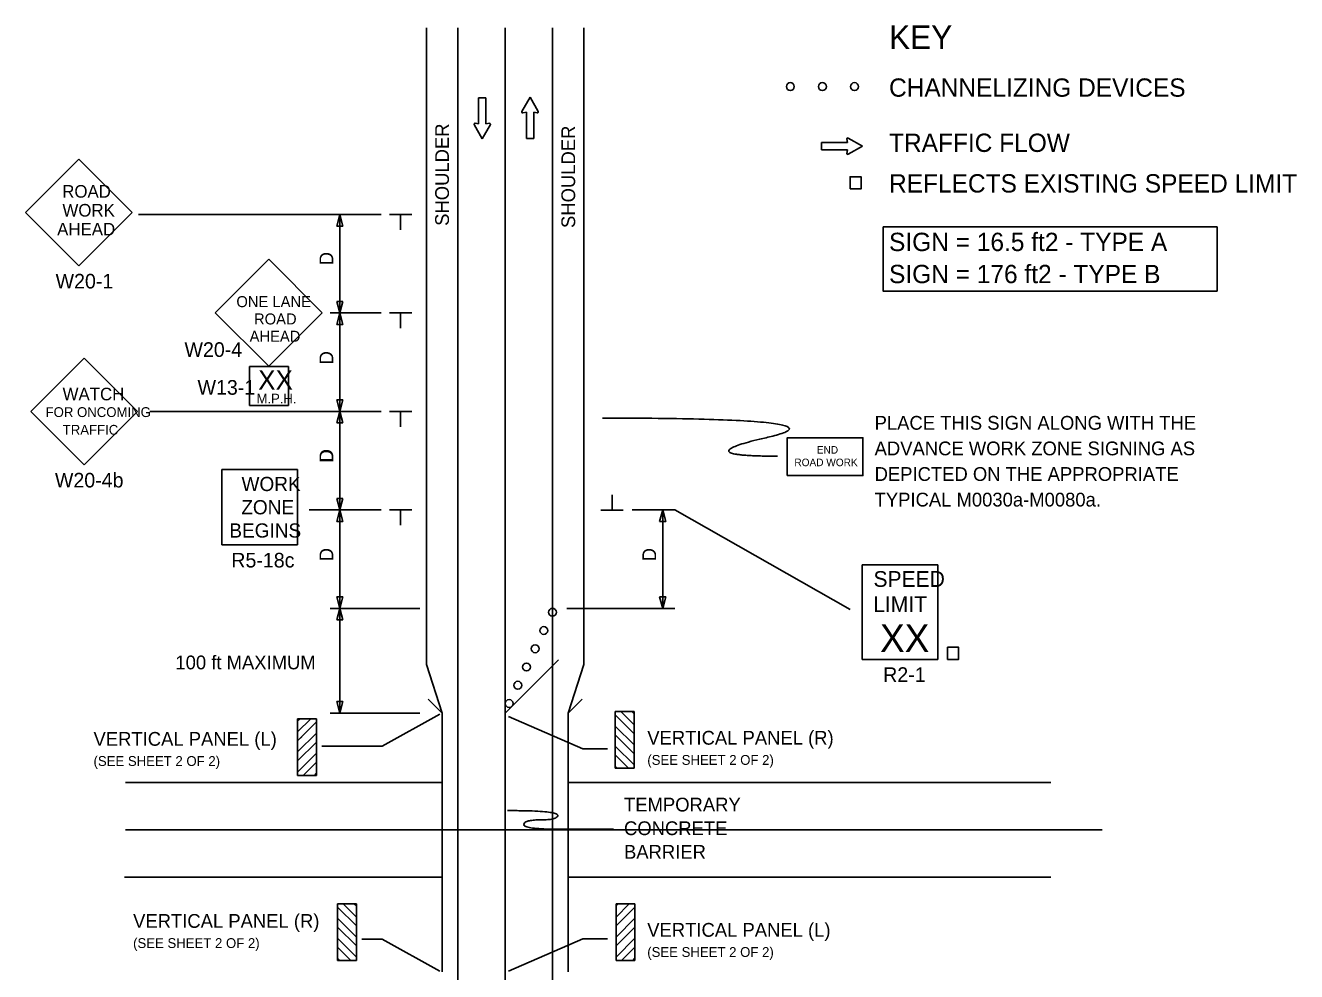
# Model space of a CAD drawing. Extents: x 16768 to 18475, y 7218 to 8259.
# Drawn here: x 16768 to 17414, y 7706 to 8187 of the extents above; entities that cross this region are included whole.
import ezdxf

# ---------------------------------------------------------------- set-up
doc = ezdxf.new("R2010")
doc.units = 0
for name, color, linetype in [('MT_SCRATCH_LEVEL_E', 7, 'Continuous'), ('PAVT_EDGE_EX', 7, 'Continuous'), ('TRAFFIC_SIGNS_PR', 7, 'Continuous'), ('TYPICAL_TEXT_DIMEN_EX', 7, 'Continuous'), ('TYPICAL_TEXT_DIMEN_PR', 7, 'Continuous')]:
    doc.layers.add(name, color=color, linetype=linetype)

msp = doc.modelspace()

# ---------------------------------------------------------------- linework, layer by layer
at = {"layer": 'MT_SCRATCH_LEVEL_E'}
for p, q in [((17002.27, 8150.09), (16998.52, 8150.09)), ((16998.52, 8150.09), (16998.52, 8136.83)), ((17002.27, 8150.09), (16998.52, 8150.09)), ((16998.52, 8150.09), (16998.52, 8136.83)), ((17002.27, 8136.83), (17002.27, 8150.09)), ((17002.27, 8136.83), (17002.27, 8150.09)), ((17024.66, 8150.35), (17020.55, 8143.11)), ((17024.66, 8150.35), (17020.55, 8143.11)), ((17028.81, 8143.11), (17024.66, 8150.35)), ((17028.81, 8143.11), (17024.66, 8150.35)), ((16996.27, 8136.47), (17000.41, 8129.22)), ((16996.27, 8136.47), (17000.41, 8129.22)), ((16998.52, 8136.83), (16996.75, 8137.15)), ((16998.52, 8136.83), (16996.75, 8137.15)), ((17000.41, 8129.22), (17004.53, 8136.47)), ((17000.41, 8129.22), (17004.53, 8136.47)), ((17004.04, 8137.15), (17002.27, 8136.83)), ((17004.04, 8137.15), (17002.27, 8136.83)), ((17021.03, 8142.43), (17022.81, 8142.74)), ((17021.03, 8142.43), (17022.81, 8142.74)), ((17022.81, 8142.74), (17022.81, 8129.49)), ((17022.81, 8142.74), (17022.81, 8129.49)), ((17026.55, 8129.49), (17026.55, 8142.74)), ((17026.55, 8142.74), (17028.33, 8142.43)), ((17026.55, 8129.49), (17026.55, 8142.74)), ((17026.55, 8142.74), (17028.33, 8142.43)), ((17022.81, 8129.49), (17026.55, 8129.49)), ((17022.81, 8129.49), (17026.55, 8129.49)), ((17185.97, 8127.41), (17172.71, 8127.41)), ((17172.71, 8127.41), (17172.71, 8123.67)), ((17185.97, 8127.41), (17172.71, 8127.41)), ((17172.71, 8127.41), (17172.71, 8123.67)), ((17172.71, 8123.67), (17185.97, 8123.67)), ((17172.71, 8123.67), (17185.97, 8123.67)), ((17185.65, 8129.19), (17185.97, 8127.41)), ((17185.65, 8129.19), (17185.97, 8127.41)), ((17185.97, 8123.67), (17185.65, 8121.89)), ((17185.97, 8123.67), (17185.65, 8121.89)), ((17193.57, 8125.56), (17186.33, 8129.67)), ((17193.57, 8125.56), (17186.33, 8129.67)), ((17186.33, 8121.41), (17193.57, 8125.56)), ((17186.33, 8121.41), (17193.57, 8125.56))]:
    msp.add_line(p, q, dxfattribs=at)
for centre, start, end in [((17020.95, 8142.89), 150.42484, 279.96381), ((17020.95, 8142.89), 150.42484, 279.96381), ((17028.4, 8142.89), 260.03619, 29.77312), ((17028.4, 8142.89), 260.03619, 29.77312), ((16996.68, 8136.69), 80.03619, 209.77312), ((16996.68, 8136.69), 80.03619, 209.77312), ((17004.12, 8136.69), 330.42484, 99.96381), ((17004.12, 8136.69), 330.42484, 99.96381), ((17186.11, 8129.26), 60.42484, 189.96381), ((17186.11, 8129.26), 60.42484, 189.96381), ((17186.11, 8121.82), 170.03619, 299.77312), ((17186.11, 8121.82), 170.03619, 299.77312)]:
    msp.add_arc(centre, 0.463, start, end, dxfattribs=at)
at = {"layer": 'PAVT_EDGE_EX'}
for p, q in [((16972.07, 8185.68), (16972.07, 7862.31)), ((16988.07, 8185.68), (16988.07, 7363.75)), ((17012.07, 8185.68), (17012.07, 7363.75)), ((17036.07, 8185.68), (17036.07, 7363.75)), ((17052.07, 8185.68), (17052.07, 7862.31)), ((16972.07, 7862.31), (16980.07, 7837.6)), ((17012.07, 7837.6), (17039.08, 7864.62)), ((17044.07, 7837.6), (17052.07, 7862.31)), ((16980.07, 7837.6), (16973, 7844.68)), ((17044.07, 7837.6), (17051.14, 7844.68)), ((16980.07, 7837.6), (16980.07, 7706.21)), ((17012.07, 7837.6), (17012.07, 7706.21)), ((17044.07, 7837.6), (17044.07, 7706.21)), ((16819.22, 7802.34), (16980.07, 7802.34)), ((16819.22, 7802.34), (16980.07, 7802.34)), ((17044.07, 7802.34), (17289.26, 7802.34)), ((16819.22, 7778.34), (17315.26, 7778.34)), ((16818.7, 7754.34), (16980.07, 7754.34)), ((17044.07, 7754.34), (17289.26, 7754.34))]:
    msp.add_line(p, q, dxfattribs=at)
for points in [[(17012.07, 8185.68), (17012.07, 8160.68)], [(17012.07, 8085.68), (17012.07, 8060.68)], [(17012.07, 7985.68), (17012.07, 7960.68)], [(17012.07, 7885.68), (17012.07, 7860.68)], [(16819.22, 7778.34), (16844.22, 7778.34)], [(16919.22, 7778.34), (16944.22, 7778.34)], [(17119.22, 7778.34), (17144.22, 7778.34)], [(17219.22, 7778.34), (17244.22, 7778.34)]]:
    msp.add_lwpolyline(points, dxfattribs=at)
at = {"layer": 'TRAFFIC_SIGNS_PR'}
for p, q in [((16795.49, 8119.01), (16768.34, 8091.86)), ((16822.64, 8091.86), (16795.49, 8119.01)), ((16768.34, 8091.86), (16795.49, 8064.7)), ((16795.49, 8064.7), (16822.64, 8091.86)), ((16891.93, 8068.07), (16864.78, 8040.92)), ((16919.08, 8040.92), (16891.93, 8068.07)), ((16864.78, 8040.92), (16891.93, 8013.77)), ((16891.93, 8013.77), (16919.08, 8040.92)), ((16798.17, 8017.94), (16771.02, 7990.79)), ((16825.32, 7990.79), (16798.17, 8017.94)), ((16882.14, 8013.61), (16901.99, 8013.61)), ((16882.14, 7993.76), (16882.14, 8013.61)), ((16901.99, 7993.76), (16901.99, 8013.61)), ((16771.02, 7990.79), (16798.17, 7963.64)), ((16798.17, 7963.64), (16825.32, 7990.79)), ((16882.14, 7993.76), (16901.99, 7993.76)), ((16868.12, 7923.01), (16868.12, 7961.41)), ((16868.12, 7961.41), (16906.52, 7961.41)), ((16906.52, 7923.01), (16906.52, 7961.41)), ((16868.12, 7923.01), (16906.52, 7923.01)), ((17193.38, 7912.88), (17231.78, 7912.88)), ((17193.38, 7864.88), (17193.38, 7912.88)), ((17231.78, 7864.88), (17231.78, 7912.88)), ((17193.38, 7864.88), (17231.78, 7864.88)), ((16906.63, 7834.79), (16916.23, 7834.79)), ((16906.63, 7834.79), (16906.63, 7805.99)), ((16906.63, 7833.71), (16907.71, 7834.79)), ((16906.63, 7828.05), (16913.37, 7834.79)), ((16906.63, 7823.52), (16916.23, 7833.12)), ((16916.23, 7834.79), (16916.23, 7805.99)), ((17077.5, 7838.39), (17067.9, 7838.39)), ((17067.9, 7838.39), (17067.9, 7809.59)), ((17077.5, 7827.12), (17067.9, 7836.72)), ((17077.5, 7831.64), (17070.76, 7838.39)), ((17077.5, 7837.3), (17076.42, 7838.39)), ((17077.5, 7838.39), (17077.5, 7809.59)), ((16906.63, 7817.87), (16916.23, 7827.47)), ((17077.5, 7821.46), (17067.9, 7831.06)), ((17077.5, 7816.93), (17067.9, 7826.53)), ((16906.63, 7813.34), (16916.23, 7822.94)), ((16908.04, 7824.94), (16909.46, 7826.35)), ((17077.5, 7811.28), (17067.9, 7820.88)), ((16906.63, 7807.68), (16916.23, 7817.28)), ((17074.67, 7809.59), (17067.9, 7816.35)), ((16909.46, 7805.99), (16916.23, 7812.76)), ((16915.12, 7805.99), (16916.23, 7807.1)), ((17069.01, 7809.59), (17067.9, 7810.69)), ((17077.5, 7809.59), (17067.9, 7809.59)), ((16906.63, 7805.99), (16916.23, 7805.99)), ((16936.47, 7740.81), (16926.87, 7740.81)), ((16926.87, 7740.81), (16926.87, 7712.01)), ((16936.47, 7729.54), (16926.87, 7739.14)), ((16936.47, 7734.06), (16929.73, 7740.81)), ((16936.47, 7739.72), (16935.39, 7740.81)), ((16936.47, 7740.81), (16936.47, 7712.01)), ((17068.37, 7740.81), (17077.97, 7740.81)), ((17068.37, 7740.81), (17068.37, 7712.01)), ((17068.37, 7739.72), (17069.46, 7740.81)), ((17068.37, 7734.06), (17075.12, 7740.81)), ((17068.37, 7729.54), (17077.97, 7739.14)), ((17077.97, 7740.81), (17077.97, 7712.01)), ((16936.47, 7723.88), (16926.87, 7733.48)), ((17068.37, 7723.88), (17077.97, 7733.48)), ((17069.79, 7730.95), (17071.2, 7732.36)), ((16936.47, 7719.35), (16926.87, 7728.95)), ((16936.47, 7713.7), (16926.87, 7723.3)), ((17068.37, 7719.35), (17077.97, 7728.95)), ((17068.37, 7713.7), (17077.97, 7723.3)), ((16933.64, 7712.01), (16926.87, 7718.77)), ((17071.21, 7712.01), (17077.97, 7718.77)), ((16927.98, 7712.01), (16926.87, 7713.11)), ((16936.47, 7712.01), (16926.87, 7712.01)), ((17068.37, 7712.01), (17077.97, 7712.01)), ((17076.87, 7712.01), (17077.97, 7713.11))]:
    msp.add_line(p, q, dxfattribs=at)
for points in [[(17187.22, 8103.84), (17192.82, 8103.84), (17192.82, 8110.01), (17187.22, 8110.01)], [(17155.35, 7958.27), (17193.75, 7958.27), (17193.75, 7977.47), (17155.35, 7977.47)], [(17236.8, 7864.88), (17242.39, 7864.88), (17242.39, 7871.05), (17236.8, 7871.05)], [(16907.71, 7834.79), (16913.37, 7834.79), (16906.63, 7828.05), (16906.63, 7833.71)], [(16906.63, 7823.52), (16916.23, 7833.12), (16916.23, 7827.47), (16906.63, 7817.87)], [(17077.5, 7827.12), (17067.9, 7836.72), (17067.9, 7831.06), (17077.5, 7821.46)], [(17076.42, 7838.39), (17070.76, 7838.39), (17077.5, 7831.64), (17077.5, 7837.3)], [(17077.5, 7816.93), (17067.9, 7826.53), (17067.9, 7820.88), (17077.5, 7811.28)], [(16906.63, 7813.34), (16916.23, 7822.94), (16916.23, 7817.28), (16906.63, 7807.68)], [(17067.9, 7816.35), (17067.9, 7810.69), (17069.01, 7809.59), (17074.67, 7809.59)], [(16916.23, 7812.76), (16916.23, 7807.1), (16915.12, 7805.99), (16909.46, 7805.99)], [(16936.47, 7729.54), (16926.87, 7739.14), (16926.87, 7733.48), (16936.47, 7723.88)], [(16935.39, 7740.81), (16929.73, 7740.81), (16936.47, 7734.06), (16936.47, 7739.72)], [(17069.46, 7740.81), (17075.12, 7740.81), (17068.37, 7734.06), (17068.37, 7739.72)], [(17068.37, 7729.54), (17077.97, 7739.14), (17077.97, 7733.48), (17068.37, 7723.88)], [(16936.47, 7719.35), (16926.87, 7728.95), (16926.87, 7723.3), (16936.47, 7713.7)], [(17068.37, 7719.35), (17077.97, 7728.95), (17077.97, 7723.3), (17068.37, 7713.7)], [(16926.87, 7718.77), (16926.87, 7713.11), (16927.98, 7712.01), (16933.64, 7712.01)], [(17077.97, 7718.77), (17077.97, 7713.11), (17076.87, 7712.01), (17071.21, 7712.01)]]:
    msp.add_lwpolyline(points, close=True, dxfattribs=at)
for centre in [(17156.9, 8155.81), (17173.2, 8155.81), (17189.5, 8155.81), (17036.07, 7888.82), (17031.67, 7879.55), (17027.27, 7870.29), (17022.87, 7861.03), (17018.47, 7851.76), (17014.07, 7842.5)]:
    msp.add_circle(centre, 2, dxfattribs=at)
msp.add_open_spline([(17150.44, 7968.1), (17103.21, 7968.1), (17188.23, 7987.44), (17061.55, 7987.44)], degree=2, dxfattribs=at)
at = {"layer": 'TYPICAL_TEXT_DIMEN_EX'}
msp.add_lwpolyline([(17204.02, 8084.5), (17373.68, 8084.5), (17373.68, 8051.95), (17204.02, 8051.95)], close=True, dxfattribs=at)
at = {"layer": 'TYPICAL_TEXT_DIMEN_PR'}
for p, q in [((16825.83, 8090.82), (16949.07, 8090.82)), ((16926.5, 8084.96), (16928.07, 8090.82)), ((16928.07, 8084.96), (16926.5, 8084.96)), ((16928.07, 8090.82), (16928.07, 8040.82)), ((16928.07, 8090.82), (16929.64, 8084.96)), ((16929.64, 8084.96), (16928.07, 8084.96)), ((16953.32, 8090.82), (16964.57, 8090.82)), ((16958.94, 8090.82), (16958.94, 8083.04)), ((16928.07, 8040.82), (16926.5, 8046.68)), ((16926.5, 8046.68), (16928.07, 8046.68)), ((16928.07, 8040.82), (16926.5, 8046.68)), ((16926.5, 8046.68), (16928.07, 8046.68)), ((16928.07, 8046.68), (16929.64, 8046.68)), ((16929.64, 8046.68), (16928.07, 8040.82)), ((16928.07, 8046.68), (16929.64, 8046.68)), ((16929.64, 8046.68), (16928.07, 8040.82)), ((16923.07, 8040.82), (16949.07, 8040.82)), ((16926.5, 8034.96), (16928.07, 8040.82)), ((16928.07, 8040.82), (16928.07, 7990.82)), ((16928.07, 8040.82), (16929.64, 8034.96)), ((16953.32, 8040.82), (16964.57, 8040.82)), ((16958.94, 8040.82), (16958.94, 8033.04)), ((16928.07, 8034.96), (16926.5, 8034.96)), ((16929.64, 8034.96), (16928.07, 8034.96)), ((16928.07, 7990.82), (16926.5, 7996.68)), ((16926.5, 7996.68), (16928.07, 7996.68)), ((16928.07, 7996.68), (16929.64, 7996.68)), ((16929.64, 7996.68), (16928.07, 7990.82)), ((16831.47, 7990.82), (16949.07, 7990.82)), ((16926.5, 7984.96), (16928.07, 7990.82)), ((16928.07, 7990.82), (16929.64, 7984.96)), ((16928.07, 7990.82), (16928.07, 7940.82)), ((16953.32, 7990.82), (16964.57, 7990.82)), ((16958.94, 7990.82), (16958.94, 7983.04)), ((16928.07, 7984.96), (16926.5, 7984.96)), ((16929.64, 7984.96), (16928.07, 7984.96)), ((16928.07, 7940.82), (16926.5, 7946.68)), ((16926.5, 7946.68), (16928.07, 7946.68)), ((16928.07, 7946.68), (16929.64, 7946.68)), ((16929.64, 7946.68), (16928.07, 7940.82)), ((17066.32, 7940.76), (17066.32, 7948.54)), ((16912.51, 7940.82), (16949.07, 7940.82)), ((16926.5, 7934.96), (16928.07, 7940.82)), ((16928.07, 7940.82), (16928.07, 7890.82)), ((16928.07, 7940.82), (16929.64, 7934.96)), ((16953.32, 7940.82), (16964.57, 7940.82)), ((16958.94, 7940.82), (16958.94, 7933.04)), ((17071.94, 7940.76), (17060.69, 7940.76)), ((17076.51, 7940.82), (17098.25, 7940.82)), ((17090.5, 7934.96), (17092.07, 7940.82)), ((17092.07, 7940.82), (17092.07, 7890.82)), ((17092.07, 7940.82), (17093.64, 7934.96)), ((17098.25, 7940.82), (17187.27, 7890.31)), ((16928.07, 7934.96), (16926.5, 7934.96)), ((16929.64, 7934.96), (16928.07, 7934.96)), ((17092.07, 7934.96), (17090.5, 7934.96)), ((17093.64, 7934.96), (17092.07, 7934.96)), ((16928.07, 7890.82), (16926.5, 7896.68)), ((16926.5, 7896.68), (16928.07, 7896.68)), ((16928.07, 7896.68), (16929.64, 7896.68)), ((16929.64, 7896.68), (16928.07, 7890.82)), ((17092.07, 7890.82), (17090.5, 7896.68)), ((17090.5, 7896.68), (17092.07, 7896.68)), ((17092.07, 7896.68), (17093.64, 7896.68)), ((17093.64, 7896.68), (17092.07, 7890.82)), ((16923.07, 7890.82), (16968.77, 7890.82)), ((16926.5, 7884.96), (16928.07, 7890.82)), ((16928.07, 7884.96), (16926.5, 7884.96)), ((16928.07, 7890.82), (16929.64, 7884.96)), ((16928.07, 7890.82), (16928.07, 7837.6)), ((16929.64, 7884.96), (16928.07, 7884.96)), ((17043.43, 7890.82), (17098.25, 7890.82)), ((16928.07, 7837.6), (16926.5, 7843.47)), ((16926.5, 7843.47), (16928.07, 7843.47)), ((16928.07, 7843.47), (16929.64, 7843.47)), ((16929.64, 7843.47), (16928.07, 7837.6)), ((16923.07, 7837.6), (16968.77, 7837.6)), ((16978.79, 7837.05), (16949.54, 7820.82)), ((17013.75, 7835.85), (17051.54, 7819.41)), ((16949.54, 7820.82), (16918.95, 7820.82)), ((17051.54, 7819.41), (17064.01, 7819.41)), ((16949.54, 7722.81), (16939.28, 7722.81)), ((16978.79, 7706.58), (16949.54, 7722.81)), ((17013.75, 7706.5), (17051.54, 7722.95)), ((17051.54, 7722.95), (17064.01, 7722.95))]:
    msp.add_line(p, q, dxfattribs=at)
msp.add_open_spline([(17013.19, 7788.11), (17038.77, 7788.11), (17038.77, 7783.4), (17021.56, 7783.4), (17021.56, 7778.69), (17054.56, 7778.69), (17067.02, 7778.69)], degree=2, dxfattribs=at)

# ---------------------------------------------------------------- texts
at = {"layer": 'TRAFFIC_SIGNS_PR'}
for s, height, p in [('ROAD', 6.4, (16787.03, 8099.39)), ('WORK', 6.4, (16787.14, 8089.79)), ('AHEAD', 6.4, (16784.45, 8080.19)), ('W20-1', 7.44, (16783.66, 8053.26)), ('ONE LANE', 5.6, (16875.51, 8043.79)), ('ROAD', 5.6, (16884.46, 8034.99)), ('AHEAD', 5.6, (16882.22, 8026.19)), ('W20-4', 7.44, (16849.14, 8018.52)), ('XX', 9.925, (16886.54, 8001.83)), ('WATCH', 6.4, (16787.22, 7996.46)), ('W13-1', 7.44, (16855.77, 7999.31)), ('M.P.H.', 4.961, (16885.76, 7994.86)), ('FOR ONCOMING', 5, (16778.58, 7987.98)), ('PLACE THIS SIGN ALONG WITH THE', 7, (17199.72, 7981.54)), ('TRAFFIC', 5, (16787.28, 7978.98)), ('ADVANCE WORK ZONE SIGNING AS', 7, (17199.72, 7968.54)), ('END', 3.831, (17170.35, 7969.4)), ('ROAD WORK', 3.831, (17158.96, 7963.02)), ('DEPICTED ON THE APPROPRIATE', 7, (17199.72, 7955.54)), ('W20-4b', 7.44, (16783.32, 7952.2)), ('WORK', 7.217, (16878.12, 7950.38)), ('TYPICAL M0030a-M0080a.', 7, (17199.72, 7942.54)), ('ZONE', 7.217, (16878, 7938.57)), ('BEGINS', 7.217, (16871.93, 7926.76)), ('R5-18c', 7.44, (16872.93, 7911.57)), ('SPEED', 8, (17199.15, 7901.74)), ('LIMIT', 8, (17198.99, 7888.94)), ('XX', 14.031, (17202.49, 7868.64)), ('R2-1', 7.44, (17204.06, 7853.44))]:
    msp.add_text(s, height=height, dxfattribs=at).set_placement(p)
at = {"layer": 'TYPICAL_TEXT_DIMEN_EX'}
for s, height, p in [('KEY', 12, (17207.05, 8174.86)), ('CHANNELIZING DEVICES', 9.3, (17207.05, 8150.65)), ('TRAFFIC FLOW', 9.3, (17207.05, 8122.61)), ('REFLECTS EXISTING SPEED LIMIT', 9.3, (17207.05, 8102)), ('SIGN = 16.5 ft2 - TYPE A', 9.3, (17207.05, 8072.27)), ('SIGN = 176 ft2 - TYPE B', 9.3, (17207.05, 8055.97))]:
    msp.add_text(s, height=height, dxfattribs=at).set_placement(p)
at = {"layer": 'TYPICAL_TEXT_DIMEN_PR'}
for s, p in [('SHOULDER', (16983.49, 8085.06)), ('SHOULDER', (17047.6, 8083.98)), ('D', (16924.73, 8065.04)), ('D', (16924.73, 8014.7)), ('D', (16924.73, 7964.98)), ('D', (16924.73, 7964.7)), ('D', (16924.73, 7914.7)), ('D', (17088.73, 7914.7))]:
    msp.add_text(s, height=7, rotation=90, dxfattribs=at).set_placement(p)
for s, height, p in [('100 ft MAXIMUM', 7, (16844.52, 7859.85)), ('VERTICAL PANEL (L)', 7, (16802.93, 7821.03)), ('VERTICAL PANEL (R)', 7, (17084.25, 7821.59)), ('(SEE SHEET 2 OF 2)', 5, (16802.93, 7810.78)), ('(SEE SHEET 2 OF 2)', 5, (17084.25, 7811.34)), ('TEMPORARY', 7, (17072.42, 7787.65)), ('CONCRETE', 7, (17072.42, 7775.65)), ('BARRIER', 7, (17072.42, 7763.65)), ('VERTICAL PANEL (R)', 7, (16823.03, 7728.57)), ('VERTICAL PANEL (L)', 7, (17084.22, 7724.04)), ('(SEE SHEET 2 OF 2)', 5, (16823.03, 7718.32)), ('(SEE SHEET 2 OF 2)', 5, (17084.22, 7713.79))]:
    msp.add_text(s, height=height, dxfattribs=at).set_placement(p)

doc.saveas('drawing.dxf')
